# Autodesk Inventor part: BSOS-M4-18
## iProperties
Author: Ron Crain
Shininess: 25.0
Angle Display Precision: 2
Document Length Units: 11269
Document Angle Units: 11284
Document Time Units: 11279
Document Mass Units: 11290
Document Length Units Precision: 2
Document Angle Units Precision: 2
Compacted: True
PropertySet Name: _Private Model Information
Created: 2001-09
Part Number: BSOS-M4-18
Material: Stainless Steel, Austenitic
Description: STANDOFF, BLIND, SELF CLINCH, M4x0.7 X 18 mm
Vendor: PENN ENG. & MFG
Document SubType Name: Modeling
Designer: Ron Crain
Control State: 0
Master: False
Checked Out: False
PropertySet Name: Design Tracking Control
Density: 7.84
Volumn: 0.17245559573138858
Area: 3.4800931280430336
PropertySet Name: Model Information
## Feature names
1. Extrusion1
2. Extrusion2
3. Revolution1
4. Revolution2
5. Rectangular Pattern1
6. Hole1
7. Chamfer3
8. Chamfer4
